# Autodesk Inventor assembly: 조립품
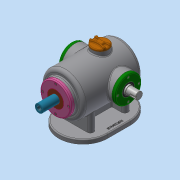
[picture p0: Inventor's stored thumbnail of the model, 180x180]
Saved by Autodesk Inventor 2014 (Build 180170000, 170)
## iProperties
Created: 2022-08
Part Number: 조립품
Document SubType Name: Assembly
Designer: dg
Author: dg
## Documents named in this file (16)
- C:\Users\dg\Desktop\620806V1008\조립품.iam
- C:\Users\dg\Desktop\620806V1008\본체.ipt
- C:\Users\dg\Desktop\620806V1008\가변스프링.ipt
- C:\Users\dg\Desktop\620806V1008\베어링 6205.ipt
- 베어링 6205.ipt
- C:\Users\dg\Desktop\620806V1008\볼트 M4x0.7.ipt
- C:\Users\dg\Desktop\620806V1008\부시.ipt
- C:\Users\dg\Desktop\620806V1008\상부 캡.ipt
- C:\Users\dg\Desktop\620806V1008\슬라이드 커버.ipt
- C:\Users\dg\Desktop\620806V1008\슬라이드.ipt
- C:\Users\dg\Desktop\620806V1008\오일실.ipt
- 오일실.ipt
- C:\Users\dg\Desktop\620806V1008\축 커버-1.ipt
- C:\Users\dg\Desktop\620806V1008\축 커버-2.ipt
- C:\Users\dg\Desktop\620806V1008\편심축.ipt
- C:\Users\dg\Desktop\620806V1008\플레이트.ipt
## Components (14 placed, 3 different names)
1. 가변스프링:1
2. M4x0.7:1
3. 플레이트:1
4. M4x0.7:2
5. M4x0.7:3
6. M4x0.7:4
7. M4x0.7:5
8. M4x0.7:6
9. M4x0.7:7
10. M4x0.7:8
11. M4x0.7:9
12. M4x0.7:10
13. M4x0.7:11
14. M4x0.7:12
